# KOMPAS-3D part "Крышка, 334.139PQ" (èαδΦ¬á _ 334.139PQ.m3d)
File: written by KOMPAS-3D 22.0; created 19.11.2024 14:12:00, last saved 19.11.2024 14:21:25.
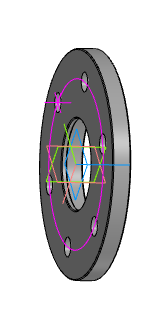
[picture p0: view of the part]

Document properties: Автор: aleksander.larionov.10@gmail.com; Полное имя файла: C:\Мои папки\Работа\Крышки, фланцы\334.139PQ\Крышка _ 334.139PQ.m3d

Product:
- Part/product: Крышка  | designation 334.139PQ
    Материал: Сталь 45 ГОСТ 1050-2013 (density 7810 kg/m3)
    Масса: 4.58251

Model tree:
1. Эскиз:1
2. Элемент вращения:1
     Угол 1 = 360
3. Эскиз:2  (with: Элемент вращения:1)
4. Отверстие:1  (with: Элемент вращения:1)
     Глубина выреза = 27; Диаметр отверстия = 14; Угол конуса дна = 118; Расстояние 1 = -85; Диаметр цековки = 20; Глубина цековки = 13
5. Массив по концентрической сетке:1  (with: Отверстие:1)  (6 pattern instances)
     Шаг 2 = 360
6. Фаска:1  (with: Элемент вращения:1)  (labels: Сталь 45 ГОСТ 1050-2013)
     Угол = 45; Длина 1 = 1; Длина 2 = 1

Expressions: 230/2; 92/2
